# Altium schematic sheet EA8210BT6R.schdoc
size 127 x 101 mm
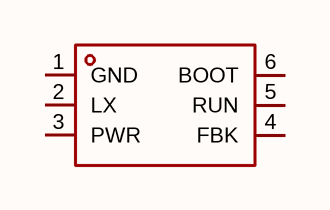
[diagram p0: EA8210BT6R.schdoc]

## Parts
U?  ea8210bt6r  [SOT-23-6_L2.9-W1.6-P0.95-LS2.8-BL-2]  (value not drawn)

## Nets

Not connected (* = marked no-connect by the designer): U? 1(GND) 2(LX) 3(PWR) 4(FBK) 5(RUN) 6(BOOT)

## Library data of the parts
U? = ea8210bt6r: 功能类型:降压型;工作电压:4.5V~21V;输出电压:600mV~17V;输出电流:2.5A;输出类型:可调;; Manufacturer: everanalog(申风); AddInBom: yes; ModelId: d6dbdad16bb04244b459daa2bbec6597; ModelTransform: 114.173,110.236,0,0,0,0,0,0,0; Function: 降压型; Output Current: 2.5A; Frequency - Switching: 400kHz~600kHz; Synchronous Rectifier: 是; Number of Outputs: 1; Topology: 降压式; Quiescent Current: 300uA; Switch tube (built-in/external): 内置; Output Type: 可调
